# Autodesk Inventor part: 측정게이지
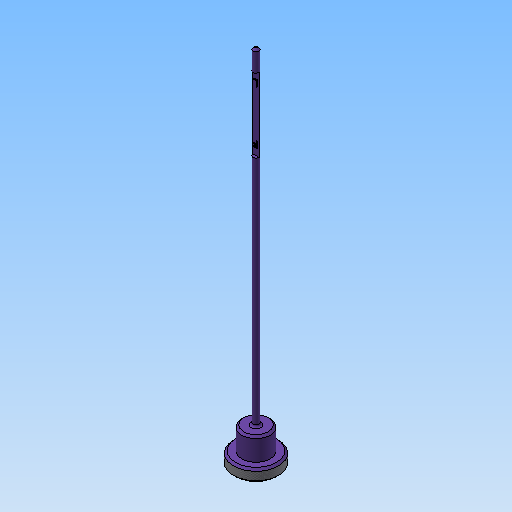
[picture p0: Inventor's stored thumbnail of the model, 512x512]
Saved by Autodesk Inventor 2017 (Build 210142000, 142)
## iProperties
Created: 2017-05
Part Number: 측정게이지
Material: 스테인리스강
Document SubType Name: Modeling
Designer: mduedu
Density: 8.08 g/cm^3
Mass: 39.5088 g
Surface Area: 29.9761 cm^2
Volume: 4.8897 cm^3
Appearance: 보라색
Author: mduedu
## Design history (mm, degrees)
sketch "스케치1"
  geometry: C1 r 11 at (0, 0); 1 further point
  constraints: 1 centre point, 1 coincident
  dimensions: "d0" = 22 diameter of C1
extrude "돌출1" new body sketch "스케치1" distance "d2" = 6; taper "d3" = 0 deg
sketch "스케치2"
  geometry: C1 r 7 at (0, 0); 1 further point
  constraints: 1 centre point, 1 coincident
  dimensions: "d4" = 14 diameter of C1
extrude "돌출2" join sketch "스케치2" distance "d5" = 11; taper "d6" = 0 deg
sketch "스케치3"
  geometry: C1 r 1.5 at (0, 0); 1 further point
  constraints: 1 centre point, 1 coincident
  dimensions: "d7" = 3 diameter of C1
extrude "돌출3" join sketch "스케치3" distance "d8" = 160; taper "d9" = 0 deg
fillet "모깎기1" dims "d10" = 1
chamfer "모따기1" distance "d11" = 1; stored, may be unused: second distance "d12" = 2, angle "d13" = 45 deg
sketch "스케치4"
  geometry: L1 (16, 7)-(17, 6) reference; L2 (6, 7)-(16, 7) reference; L3 (16, -7)-(6, -7) reference; L4 (17, -6)-(16, -7) reference; L5 (17, 6)-(17, 2.5) reference; L6 (18, 1.5)-(176, 1.5) reference; L7 (176, 1.5)-(177, 0.5) reference; L8 (177, 0.5)-(177, -0.5) reference; L9 (177, -0.5)-(176, -1.5) reference; L10 (176, -1.5)-(18, -1.5) reference; L11 (17, -2.5)-(17, -6) reference; L12 (177, 0)-(0, 0); L13 (167, 0)-(131, 0); L14 (131, 0)-(131, 1.5); L15 (131, 1.5)-(167, 1.5); L16 (167, 1.5)-(167, 0); L17 (0, 11)-(6, 11) reference; L18 (6, 11)-(6, 7) reference; L19 (6, -7)-(6, -11) reference; L20 (6, -11)-(0, -11) reference; L21 (0, -11)-(0, 11) reference; A1 r 1 centre (18, 2.5) between (17, 2.5) and (18, 1.5) reference; A2 r 1 centre (18, -2.5) between (18, -1.5) and (17, -2.5) reference
  constraints: 10 end point, 2 parallel, 2 point on line, 1 horizontal, 1 midpoint, 1 perpendicular
  dimensions: "d14" = 10 distance from line of L16 L7.end; "d15" = 36 distance between parallel lines of L14 L16
extrude "돌출4" cut sketch "스케치4" stored distance "d16" = 160; taper "d17" = 0 deg
sketch "스케치5"
  geometry: L1 (0, 0)-(3, 0) reference; L2 (3, 36)-(0, 36) reference; L3 (1.5, 0)-(1.5, 36); 3 further points
  constraints: 2 end point, 2 midpoint, 2 point on line, 2 other
  dimensions: "d18" = 5 distance from line of point (1.5, 5) L1; "d19" = 5 distance from line of point (1.5, 31) L2
feature "엠보싱1" sketch "스케치5" dims "d20" = 0.3, "d21" = 0
chamfer "모따기2" distance "d32" = 1; stored, may be unused: second distance "d33" = 2, angle "d34" = 45 deg
node "솔리드1"
node "절단 모서리 투영1"
